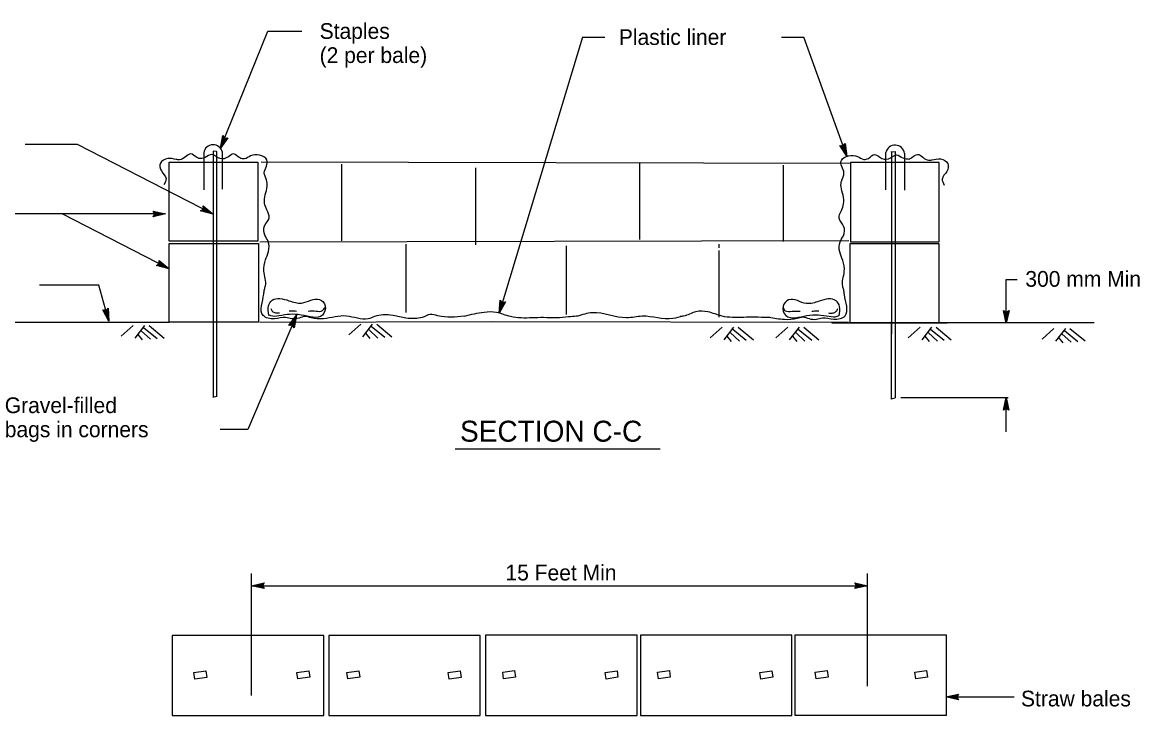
# Model space of a CAD drawing. Extents: x 6707406 to 6714471, y 1868570 to 1872341.
# Drawn here: x 6709428 to 6709939, y 1868969 to 1869287 of the extents above; entities that cross this region are included whole.
import ezdxf

# ---------------------------------------------------------------- set-up
doc = ezdxf.new("R2010")
doc.units = 0
for name, color, linetype in [('1 Control', 7, 'Continuous'), ('56 Stg 3 Anno', 7, 'Continuous'), ('57 Undefined', 7, 'Continuous'), ('59 Soundwall Ann', 7, 'Continuous'), ('60 Nongeo Data', 7, 'Continuous')]:
    doc.layers.add(name, color=color, linetype=linetype)

msp = doc.modelspace()

# ---------------------------------------------------------------- linework, layer by layer
at = {"layer": '1 Control'}
for p, q in [((6709487.66, 1869200.39), (6709487.66, 1869200.39)), ((6709487.66, 1869197.83), (6709487.66, 1869197.83)), ((6709493.42, 1869199.11), (6709493.42, 1869199.11))]:
    msp.add_line(p, q, dxfattribs=at)
msp.add_lwpolyline([(6709487.66, 1869200.39), (6709493.42, 1869199.11), (6709487.66, 1869197.83), (6709487.86, 1869198.17), (6709492.08, 1869199.1), (6709487.86, 1869200.05), (6709488.07, 1869199.71), (6709490.77, 1869199.11), (6709488.07, 1869198.51), (6709488.27, 1869198.85), (6709489.44, 1869199.11), (6709488.27, 1869199.37), (6709488.43, 1869199.11), (6709487.66, 1869197.83), (6709488.43, 1869199.11)], close=True, dxfattribs=at)
at = {"layer": '56 Stg 3 Anno'}
for p, q in [((6709518.59, 1869229.13), (6709540.27, 1869282.85)), ((6709540.27, 1869282.85), (6709555.82, 1869282.85)), ((6709684.34, 1869280.08), (6709646.13, 1869153.7)), ((6709684.34, 1869280.08), (6709694.46, 1869280.08)), ((6709775.45, 1869280.08), (6709785.57, 1869280.08)), ((6709805.29, 1869225.52), (6709785.57, 1869280.08)), ((6709518.59, 1869229.13), (6709519.56, 1869234.95)), ((6709521.94, 1869233.99), (6709518.59, 1869229.13)), ((6709519.08, 1869230.37), (6709519.79, 1869234.61)), ((6709521.54, 1869233.92), (6709519.08, 1869230.36)), ((6709519.56, 1869234.95), (6709519.56, 1869234.95)), ((6709519.56, 1869234.95), (6709520.46, 1869233.76)), ((6709519.58, 1869231.59), (6709520.04, 1869234.33)), ((6709521.14, 1869233.85), (6709519.58, 1869231.59)), ((6709520.08, 1869232.82), (6709520.27, 1869233.99)), ((6709520.77, 1869233.81), (6709520.08, 1869232.82)), ((6709520.46, 1869233.76), (6709521.94, 1869233.99)), ((6709521.94, 1869233.99), (6709521.94, 1869233.99)), ((6709453.01, 1869230.92), (6709429.07, 1869230.92)), ((6709515.11, 1869199.03), (6709453.01, 1869230.92)), ((6709518.59, 1869229.13), (6709518.59, 1869229.13)), ((6709805.29, 1869225.52), (6709802.13, 1869230.5)), ((6709802.13, 1869230.5), (6709802.13, 1869230.5)), ((6709802.13, 1869230.5), (6709803.59, 1869230.21)), ((6709804.83, 1869226.77), (6709802.53, 1869230.41)), ((6709804.39, 1869228.01), (6709802.9, 1869230.36)), ((6709803.94, 1869229.26), (6709803.3, 1869230.27)), ((6709803.59, 1869230.21), (6709804.54, 1869231.37)), ((6709803.79, 1869230.46), (6709803.94, 1869229.26)), ((6709804.04, 1869230.73), (6709804.39, 1869228.01)), ((6709804.29, 1869231.06), (6709804.84, 1869226.77)), ((6709804.54, 1869231.37), (6709804.54, 1869231.37)), ((6709804.54, 1869231.37), (6709805.29, 1869225.52)), ((6709805.29, 1869225.52), (6709805.29, 1869225.52)), ((6709510.67, 1869201.31), (6709510.58, 1869202.8)), ((6709510.58, 1869202.8), (6709510.58, 1869202.8)), ((6709510.58, 1869202.8), (6709515.11, 1869199.03)), ((6709493.42, 1869199.11), (6709417.73, 1869199.11)), ((6709494.96, 1869174), (6709446.06, 1869199.11)), ((6709509.4, 1869200.52), (6709510.67, 1869201.31)), ((6709515.11, 1869199.03), (6709509.4, 1869200.52)), ((6709509.4, 1869200.52), (6709509.4, 1869200.52)), ((6709513.92, 1869199.64), (6709509.76, 1869200.73)), ((6709512.75, 1869200.24), (6709510.07, 1869200.95)), ((6709511.57, 1869200.85), (6709510.42, 1869201.15)), ((6709510.6, 1869202.41), (6709513.93, 1869199.63)), ((6709510.65, 1869202), (6709512.75, 1869200.24)), ((6709510.65, 1869201.62), (6709511.57, 1869200.85)), ((6709515.11, 1869199.03), (6709515.11, 1869199.03)), ((6709490.52, 1869176.28), (6709490.42, 1869177.77)), ((6709490.42, 1869177.77), (6709490.42, 1869177.77)), ((6709490.42, 1869177.77), (6709494.96, 1869174)), ((6709490.45, 1869177.37), (6709493.78, 1869174.6)), ((6709489.25, 1869175.49), (6709490.52, 1869176.28)), ((6709494.96, 1869174), (6709489.25, 1869175.49)), ((6709489.25, 1869175.49), (6709489.25, 1869175.49)), ((6709493.77, 1869174.6), (6709489.61, 1869175.7)), ((6709492.6, 1869175.21), (6709489.91, 1869175.91)), ((6709491.42, 1869175.82), (6709490.27, 1869176.12)), ((6709490.49, 1869176.96), (6709492.6, 1869175.21)), ((6709490.49, 1869176.59), (6709491.42, 1869175.82)), ((6709494.96, 1869174), (6709494.96, 1869174)), ((6709878.28, 1869169.1), (6709883.25, 1869169.1)), ((6709878.28, 1869149.12), (6709878.28, 1869169.1)), ((6709462.84, 1869166.47), (6709435.69, 1869166.47)), ((6709467.42, 1869150.02), (6709462.84, 1869166.47)), ((6709646.13, 1869153.7), (6709646.57, 1869159.58)), ((6709649.03, 1869158.84), (6709646.13, 1869153.7)), ((6709646.51, 1869154.98), (6709646.84, 1869159.27)), ((6709648.64, 1869158.74), (6709646.51, 1869154.97)), ((6709646.57, 1869159.58), (6709646.57, 1869159.58)), ((6709646.57, 1869159.58), (6709647.57, 1869158.48)), ((6709646.9, 1869156.24), (6709647.11, 1869159.01)), ((6709648.24, 1869158.63), (6709646.9, 1869156.24)), ((6709647.28, 1869157.51), (6709647.37, 1869158.69)), ((6709647.88, 1869158.56), (6709647.28, 1869157.51)), ((6709647.57, 1869158.48), (6709649.03, 1869158.84)), ((6709649.03, 1869158.84), (6709649.03, 1869158.84)), ((6709467.42, 1869150.02), (6709464.64, 1869155.23)), ((6709464.64, 1869155.23), (6709464.64, 1869155.23)), ((6709464.64, 1869155.23), (6709466.08, 1869154.83)), ((6709467.06, 1869151.31), (6709465.04, 1869155.11)), ((6709466.71, 1869152.58), (6709465.4, 1869155.03)), ((6709466.35, 1869153.86), (6709465.8, 1869154.91)), ((6709466.08, 1869154.83), (6709467.11, 1869155.92)), ((6709466.29, 1869155.07), (6709466.35, 1869153.86)), ((6709466.57, 1869155.32), (6709466.71, 1869152.58)), ((6709466.84, 1869155.63), (6709467.06, 1869151.3)), ((6709467.11, 1869155.92), (6709467.11, 1869155.92)), ((6709467.11, 1869155.92), (6709467.42, 1869150.02)), ((6709553.27, 1869152.72), (6709531.07, 1869100.43)), ((6709549.84, 1869147.92), (6709553.27, 1869152.72)), ((6709550.23, 1869147.98), (6709552.75, 1869151.5)), ((6709553.27, 1869152.72), (6709552.2, 1869146.92)), ((6709553.27, 1869152.72), (6709553.27, 1869152.72)), ((6709646.13, 1869153.7), (6709646.13, 1869153.7)), ((6709878.28, 1869149.12), (6709877, 1869154.88)), ((6709877, 1869154.88), (6709877, 1869154.88)), ((6709877, 1869154.88), (6709878.28, 1869154.11)), ((6709878.27, 1869150.46), (6709877.34, 1869154.66)), ((6709878.28, 1869151.77), (6709877.68, 1869154.49)), ((6709878.28, 1869153.1), (6709878.02, 1869154.26)), ((6709878.28, 1869154.11), (6709879.56, 1869154.88)), ((6709879.56, 1869154.88), (6709878.28, 1869149.12)), ((6709879.22, 1869154.67), (6709878.28, 1869150.45)), ((6709878.88, 1869154.45), (6709878.28, 1869151.77)), ((6709878.54, 1869154.28), (6709878.28, 1869153.1)), ((6709879.56, 1869154.88), (6709879.56, 1869154.88)), ((6709467.42, 1869150.02), (6709467.42, 1869150.02)), ((6709551.32, 1869148.12), (6709549.84, 1869147.92)), ((6709549.84, 1869147.92), (6709549.84, 1869147.92)), ((6709550.64, 1869148.05), (6709552.23, 1869150.28)), ((6709551.01, 1869148.08), (6709551.71, 1869149.06)), ((6709552.2, 1869146.92), (6709551.32, 1869148.12)), ((6709551.71, 1869149.06), (6709551.5, 1869147.89)), ((6709552.23, 1869150.28), (6709551.73, 1869147.55)), ((6709552.75, 1869151.49), (6709551.97, 1869147.26)), ((6709552.2, 1869146.92), (6709552.2, 1869146.92)), ((6709878.28, 1869149.12), (6709878.28, 1869149.12)), ((6709830.05, 1869114.95), (6709879.14, 1869114.95)), ((6709876.99, 1869109.19), (6709878.28, 1869114.95)), ((6709877.33, 1869109.4), (6709878.27, 1869113.63)), ((6709877.68, 1869109.62), (6709878.27, 1869112.3)), ((6709878.01, 1869109.79), (6709878.27, 1869110.97)), ((6709878.27, 1869112.3), (6709878.87, 1869109.59)), ((6709878.27, 1869110.97), (6709878.53, 1869109.81)), ((6709878.28, 1869114.95), (6709878.28, 1869114.95)), ((6709878.28, 1869114.95), (6709879.55, 1869109.19)), ((6709878.28, 1869099.27), (6709878.28, 1869114.95)), ((6709878.28, 1869113.61), (6709879.21, 1869109.42)), ((6709878.28, 1869109.96), (6709876.99, 1869109.19)), ((6709876.99, 1869109.19), (6709876.99, 1869109.19)), ((6709879.55, 1869109.19), (6709878.28, 1869109.96)), ((6709879.55, 1869109.19), (6709879.55, 1869109.19)), ((6709531.07, 1869100.43), (6709518.32, 1869100.43)), ((6709532.76, 1868978.54), (6709532.76, 1869034.49)), ((6709814.79, 1868982.86), (6709814.79, 1869034.49)), ((6709532.76, 1869028.82), (6709538.52, 1869030.09)), ((6709532.76, 1869028.82), (6709538.52, 1869030.09)), ((6709532.76, 1869028.82), (6709814.79, 1869028.82)), ((6709538.52, 1869027.53), (6709532.76, 1869028.82)), ((6709532.76, 1869028.82), (6709532.76, 1869028.82)), ((6709538.52, 1869027.53), (6709532.76, 1869028.82)), ((6709532.76, 1869028.82), (6709532.76, 1869028.82)), ((6709538.32, 1869027.87), (6709534.09, 1869028.81)), ((6709538.32, 1869027.87), (6709534.09, 1869028.81)), ((6709534.1, 1869028.82), (6709538.3, 1869029.75)), ((6709534.1, 1869028.82), (6709538.3, 1869029.75)), ((6709535.42, 1869028.81), (6709538.13, 1869029.41)), ((6709535.42, 1869028.81), (6709538.13, 1869029.41)), ((6709538.09, 1869028.22), (6709535.42, 1869028.81)), ((6709538.09, 1869028.22), (6709535.42, 1869028.81)), ((6709536.74, 1869028.81), (6709537.9, 1869029.07)), ((6709536.74, 1869028.81), (6709537.9, 1869029.07)), ((6709537.92, 1869028.55), (6709536.74, 1869028.81)), ((6709537.92, 1869028.55), (6709536.74, 1869028.81)), ((6709538.52, 1869030.09), (6709537.76, 1869028.82)), ((6709538.52, 1869030.09), (6709537.76, 1869028.82)), ((6709537.76, 1869028.82), (6709538.52, 1869027.53)), ((6709537.76, 1869028.82), (6709538.52, 1869027.53)), ((6709538.52, 1869030.09), (6709538.52, 1869030.09)), ((6709538.52, 1869030.09), (6709538.52, 1869030.09)), ((6709809.8, 1869028.82), (6709809.03, 1869030.1)), ((6709809.03, 1869030.1), (6709809.03, 1869030.1)), ((6709809.03, 1869030.1), (6709814.79, 1869028.82)), ((6709814.79, 1869028.82), (6709809.03, 1869027.54)), ((6709809.03, 1869027.54), (6709809.8, 1869028.82)), ((6709809.24, 1869029.76), (6709813.47, 1869028.82)), ((6709813.46, 1869028.81), (6709809.26, 1869027.88)), ((6709812.14, 1869028.82), (6709809.43, 1869028.22)), ((6709809.47, 1869029.41), (6709812.14, 1869028.82)), ((6709809.64, 1869029.08), (6709810.82, 1869028.82)), ((6709810.82, 1869028.82), (6709809.66, 1869028.56)), ((6709814.79, 1869028.82), (6709814.79, 1869028.82)), ((6709538.52, 1869027.53), (6709538.52, 1869027.53)), ((6709538.52, 1869027.53), (6709538.52, 1869027.53)), ((6709809.03, 1869027.54), (6709809.03, 1869027.54)), ((6709850.7, 1868977.91), (6709856.46, 1868979.18)), ((6709850.7, 1868977.91), (6709881.9, 1868977.91)), ((6709856.46, 1868976.62), (6709850.7, 1868977.91)), ((6709850.7, 1868977.91), (6709850.7, 1868977.91)), ((6709856.25, 1868976.96), (6709852.03, 1868977.91)), ((6709852.04, 1868977.91), (6709856.24, 1868978.84)), ((6709853.35, 1868977.91), (6709856.07, 1868978.51)), ((6709856.03, 1868977.31), (6709853.35, 1868977.91)), ((6709854.68, 1868977.9), (6709855.84, 1868978.16)), ((6709855.86, 1868977.64), (6709854.68, 1868977.9)), ((6709856.46, 1868979.18), (6709855.69, 1868977.91)), ((6709855.69, 1868977.91), (6709856.46, 1868976.62)), ((6709856.46, 1868979.18), (6709856.46, 1868979.18)), ((6709856.46, 1868976.62), (6709856.46, 1868976.62))]:
    msp.add_line(p, q, dxfattribs=at)
at = {"layer": '57 Undefined'}
msp.add_line((6709625.91, 1869091.56), (6709719.89, 1869091.56), dxfattribs=at)
at = {"layer": '59 Soundwall Ann'}
for p, q in [((6709478.57, 1869148.02), (6709473.1, 1869143.15)), ((6709483.77, 1869147.99), (6709479.25, 1869142.24)), ((6709483.32, 1869147.13), (6709489.51, 1869142.03)), ((6709485.88, 1869147.96), (6709492.8, 1869142.26)), ((6709582.79, 1869148.59), (6709577.31, 1869143.72)), ((6709587.99, 1869148.55), (6709583.47, 1869142.81)), ((6709587.54, 1869147.69), (6709593.73, 1869142.6)), ((6709590.09, 1869148.53), (6709597.02, 1869142.83)), ((6709748.28, 1869147.22), (6709742.8, 1869142.35)), ((6709753.47, 1869147.19), (6709748.95, 1869141.44)), ((6709755.58, 1869147.17), (6709762.5, 1869141.47)), ((6709778.3, 1869147.22), (6709772.82, 1869142.35)), ((6709783.49, 1869147.19), (6709778.97, 1869141.44)), ((6709785.6, 1869147.17), (6709792.52, 1869141.47)), ((6709838.9, 1869147.22), (6709833.42, 1869142.35)), ((6709844.09, 1869147.19), (6709839.58, 1869141.44)), ((6709846.2, 1869147.17), (6709853.13, 1869141.47)), ((6709900.15, 1869146.66), (6709894.68, 1869141.78)), ((6709905.35, 1869146.62), (6709900.83, 1869140.87)), ((6709907.46, 1869146.6), (6709914.38, 1869140.9)), ((6709480.69, 1869143.89), (6709482.67, 1869141.46)), ((6709482.19, 1869145.54), (6709486.42, 1869141.69)), ((6709584.91, 1869144.46), (6709586.89, 1869142.03)), ((6709586.41, 1869146.11), (6709590.64, 1869142.26)), ((6709750.39, 1869143.09), (6709752.37, 1869140.66)), ((6709751.89, 1869144.74), (6709756.12, 1869140.89)), ((6709753.03, 1869146.33), (6709759.22, 1869141.23)), ((6709780.41, 1869143.09), (6709782.39, 1869140.66)), ((6709781.91, 1869144.74), (6709786.14, 1869140.89)), ((6709783.05, 1869146.33), (6709789.23, 1869141.23)), ((6709841.02, 1869143.09), (6709843, 1869140.66)), ((6709842.52, 1869144.74), (6709846.75, 1869140.89)), ((6709843.65, 1869146.33), (6709849.84, 1869141.23)), ((6709902.27, 1869142.52), (6709904.25, 1869140.09)), ((6709903.77, 1869144.17), (6709908, 1869140.32)), ((6709904.9, 1869145.76), (6709911.09, 1869140.66))]:
    msp.add_line(p, q, dxfattribs=at)
at = {"layer": '60 Nongeo Data'}
for p, q in [((6709823.86, 1869229.14), (6709823.86, 1869229.14)), ((6709510.85, 1869227.15), (6709510.85, 1869210.15)), ((6709515.11, 1869227.84), (6709515.11, 1869115.08)), ((6709516.73, 1869227.73), (6709515.11, 1869227.84)), ((6709516.73, 1869227.61), (6709516.73, 1869227.84)), ((6709516.73, 1869227.61), (6709516.73, 1869115.4)), ((6709519.43, 1869210.39), (6709519.43, 1869227.39)), ((6709823.11, 1869210.18), (6709823.11, 1869227.18)), ((6709825.8, 1869227.4), (6709825.8, 1869227.63)), ((6709825.8, 1869227.51), (6709827.42, 1869227.63)), ((6709825.8, 1869227.4), (6709825.8, 1869144.14)), ((6709827.42, 1869227.63), (6709827.42, 1869144.14)), ((6709831.68, 1869226.94), (6709831.68, 1869209.94)), ((6709537.12, 1869222.92), (6709807.06, 1869222.39)), ((6709573.96, 1869221.95), (6709573.96, 1869186.7)), ((6709635.34, 1869220.22), (6709635.34, 1869184.96)), ((6709710.44, 1869222.62), (6709710.44, 1869187.36)), ((6709776.08, 1869221.47), (6709776.08, 1869186.5)), ((6709536.5, 1869186.34), (6709806.17, 1869186.87)), ((6709603.37, 1869185.26), (6709603.37, 1869153.89)), ((6709676.87, 1869184.46), (6709676.87, 1869153.09)), ((6709746.68, 1869185.25), (6709746.68, 1869183.49)), ((6709746.68, 1869182.27), (6709746.68, 1869151.86)), ((6709365.05, 1869149.57), (6709494.96, 1869149.57)), ((6709536.5, 1869149.54), (6709643.26, 1869149.81)), ((6709806.03, 1869149.33), (6709643.26, 1869149.74)), ((6709825.64, 1869149.68), (6709825.64, 1869114.31)), ((6709827.47, 1869149.68), (6709827.47, 1869114.82)), ((6709847.58, 1869149.35), (6709918.59, 1869149.35)), ((6709516.82, 1869115.44), (6709514.99, 1869115.08)), ((6709827.47, 1869114.64), (6709825.64, 1869114.28))]:
    msp.add_line(p, q, dxfattribs=at)
for points in [[(6709494.96, 1869222.81), (6709535.59, 1869222.81), (6709535.59, 1869186.56), (6709494.96, 1869186.56)], [(6709847.58, 1869222.59), (6709806.95, 1869222.59), (6709806.95, 1869186.34), (6709847.58, 1869186.34)], [(6709494.96, 1869185.61), (6709535.89, 1869185.61), (6709535.89, 1869149.57), (6709494.96, 1869149.57)], [(6709847.58, 1869185.4), (6709806.64, 1869185.4), (6709806.64, 1869149.35), (6709847.58, 1869149.35)], [(6709496.47, 1868969.31), (6709565.82, 1868969.31), (6709565.82, 1869006.05), (6709496.47, 1869006.05)], [(6709568.1, 1868969.31), (6709637.45, 1868969.31), (6709637.45, 1869006.05), (6709568.1, 1869006.05)], [(6709639.88, 1868969.38), (6709709.24, 1868969.38), (6709709.24, 1869006.12), (6709639.88, 1869006.12)], [(6709710.76, 1868969.38), (6709780.11, 1868969.38), (6709780.11, 1869006.12), (6709710.76, 1869006.12)], [(6709781.56, 1868969.48), (6709850.91, 1868969.48), (6709850.91, 1869006.23), (6709781.56, 1869006.23)], [(6709506.39, 1868989.01), (6709511.83, 1868989.8), (6709512.26, 1868986.8), (6709506.83, 1868986.01)], [(6709553.5, 1868989.11), (6709558.93, 1868989.9), (6709559.37, 1868986.9), (6709553.94, 1868986.11)], [(6709576.44, 1868989.11), (6709581.87, 1868989.9), (6709582.31, 1868986.9), (6709576.87, 1868986.11)], [(6709622.79, 1868989.01), (6709628.22, 1868989.8), (6709628.66, 1868986.8), (6709623.23, 1868986.01)], [(6709647.74, 1868989.18), (6709653.17, 1868989.97), (6709653.6, 1868986.97), (6709648.17, 1868986.18)], [(6709694.65, 1868989.08), (6709700.08, 1868989.87), (6709700.51, 1868986.87), (6709695.08, 1868986.08)], [(6709718.61, 1868989.18), (6709724.04, 1868989.97), (6709724.48, 1868986.97), (6709719.05, 1868986.18)], [(6709765.52, 1868989.08), (6709770.95, 1868989.87), (6709771.39, 1868986.87), (6709765.95, 1868986.08)], [(6709790.84, 1868989.18), (6709796.27, 1868989.97), (6709796.71, 1868986.97), (6709791.27, 1868986.18)], [(6709836.41, 1868989.18), (6709841.84, 1868989.97), (6709842.27, 1868986.97), (6709836.84, 1868986.18)]]:
    msp.add_lwpolyline(points, close=True, dxfattribs=at)
msp.add_lwpolyline([(6709798.43, 1869149.68), (6709798.43, 1869149.17), (6709851.25, 1869149.17)], dxfattribs=at)
for centre, start, end in [((6709515.15, 1869226.45), 12.0716, 172.0722), ((6709827.39, 1869226.24), 7.9278, 167.9284)]:
    msp.add_arc(centre, 4.36, start, end, dxfattribs=at)
for points in [[(6709508.47, 1869224.6), (6709507.47, 1869225.08), (6709504.91, 1869226.59), (6709502.49, 1869225.23), (6709499.77, 1869223.88), (6709498.26, 1869224.03), (6709494.34, 1869224.48), (6709491.02, 1869222.37), (6709491.47, 1869218.75), (6709493.58, 1869215.28), (6709492.65, 1869212.52)], [(6709630.08, 1869152.2), (6709618.1, 1869152.41), (6709614.47, 1869153.02), (6709610.85, 1869151.66), (6709607.53, 1869151.21), (6709603.45, 1869151.36), (6709597.56, 1869152.57), (6709593.04, 1869152.87), (6709589.11, 1869152.11), (6709586.09, 1869151.06), (6709576.22, 1869152.3), (6709565.71, 1869151.06), (6709559.97, 1869151.51), (6709557.41, 1869152.11), (6709554.53, 1869151.38), (6709551.17, 1869151.07), (6709548.42, 1869151.68), (6709543.22, 1869151.07), (6709538.03, 1869152.6), (6709538.34, 1869162.38), (6709538.64, 1869164.52), (6709539.14, 1869166.13), (6709538.38, 1869172.91), (6709539.14, 1869178.03), (6709540.5, 1869181.95), (6709540.35, 1869186.47), (6709538.84, 1869189.33), (6709538.68, 1869193.7), (6709540.8, 1869197.31), (6709539.74, 1869200.93), (6709538.68, 1869203.94), (6709538.99, 1869207.86), (6709539.89, 1869211.78), (6709539.59, 1869214.64), (6709538.53, 1869217.96), (6709539.59, 1869220.97), (6709539.74, 1869223.83), (6709536.42, 1869225.94), (6709532.34, 1869225.64), (6709529.48, 1869224.29), (6709527.36, 1869224.74), (6709524.49, 1869226.55), (6709522.14, 1869225.24), (6709518.21, 1869224.49), (6709514.44, 1869226.3), (6709511.57, 1869224.94), (6709508.4, 1869224.43)], [(6709769.53, 1869151.74), (6709776.83, 1869150.85), (6709782.56, 1869151.3), (6709785.13, 1869151.9), (6709788.01, 1869151.17), (6709791.37, 1869150.86), (6709794.12, 1869151.47), (6709799.31, 1869150.86), (6709804.51, 1869152.39), (6709804.2, 1869162.17), (6709803.89, 1869164.31), (6709803.4, 1869165.91), (6709804.15, 1869172.69), (6709803.4, 1869177.82), (6709802.04, 1869181.73), (6709802.19, 1869186.25), (6709803.7, 1869189.12), (6709803.85, 1869193.49), (6709801.74, 1869197.1), (6709802.79, 1869200.72), (6709803.85, 1869203.73), (6709803.55, 1869207.65), (6709802.64, 1869211.57), (6709802.94, 1869214.43), (6709804, 1869217.74), (6709802.94, 1869220.76), (6709802.79, 1869223.62), (6709806.12, 1869225.73), (6709810.19, 1869225.43), (6709813.06, 1869224.07), (6709815.17, 1869224.52), (6709818.04, 1869226.33), (6709820.4, 1869225.03), (6709824.32, 1869224.28), (6709828.1, 1869226.09), (6709830.97, 1869224.73), (6709834.14, 1869224.22)], [(6709834.06, 1869224.39), (6709835.06, 1869224.87), (6709837.63, 1869226.38), (6709840.04, 1869225.02), (6709842.76, 1869223.67), (6709844.27, 1869223.82), (6709848.2, 1869224.27), (6709851.52, 1869222.16), (6709851.07, 1869218.54), (6709848.95, 1869215.07), (6709849.88, 1869212.31)], [(6709540.73, 1869152.62), (6709540.54, 1869156.99), (6709542.19, 1869159.54), (6709549.85, 1869159.36), (6709555.69, 1869158.26), (6709563.9, 1869159.9), (6709566.46, 1869156.99), (6709565.18, 1869152.8), (6709555.51, 1869152.8), (6709545.29, 1869152.43), (6709541.64, 1869152.43), (6709540.91, 1869152.8)], [(6709801.81, 1869152.4), (6709801.99, 1869156.78), (6709800.35, 1869159.33), (6709792.68, 1869159.15), (6709786.84, 1869158.05), (6709778.63, 1869159.69), (6709776.08, 1869156.78), (6709777.35, 1869152.59), (6709787.03, 1869152.59), (6709797.25, 1869152.22), (6709800.9, 1869152.22), (6709801.63, 1869152.59)], [(6709541.52, 1869155.82), (6709542.25, 1869154.54), (6709543.71, 1869153.82), (6709545.53, 1869153.82)], [(6709550.03, 1869154.73), (6709552.04, 1869154.73), (6709553.32, 1869154.55)], [(6709558.67, 1869154.61), (6709562.32, 1869154.61), (6709565.24, 1869154.79), (6709566.34, 1869156.43)], [(6709681.79, 1869152.4), (6709681.51, 1869152.34), (6709677.88, 1869151.89), (6709672.45, 1869151.44), (6709666.41, 1869151.59), (6709656.15, 1869151.44), (6709651.32, 1869152.04), (6709644.83, 1869154), (6709639.24, 1869154), (6709630.03, 1869152.19)], [(6709730.16, 1869152.32), (6709725.65, 1869151.13), (6709711.6, 1869152.22), (6709704.48, 1869151.49), (6709688.79, 1869153.86), (6709681.77, 1869152.08)], [(6709770.04, 1869151.7), (6709769.31, 1869151.67), (6709763.27, 1869151.82), (6709753, 1869151.67), (6709748.17, 1869152.28), (6709741.68, 1869154.24), (6709736.1, 1869154.24), (6709730.51, 1869152.28), (6709728.95, 1869152.06)], [(6709783.86, 1869154.4), (6709780.21, 1869154.4), (6709777.29, 1869154.58), (6709776.2, 1869156.22)], [(6709792.5, 1869154.52), (6709790.49, 1869154.52), (6709789.22, 1869154.34)], [(6709801.02, 1869155.61), (6709800.29, 1869154.33), (6709798.83, 1869153.6), (6709797, 1869153.6)]]:
    msp.add_spline(points, degree=3, dxfattribs=at)

# ---------------------------------------------------------------- texts
at = {"layer": '57 Undefined'}
for s, height, p in [('Staples', 7.2, (6709563.92, 1869279.25)), ('Plastic liner', 7.2002, (6709700.91, 1869276.48)), ('(2 per bale)', 7.2002, (6709563.92, 1869268.21)), ('300 mm Min', 7.2, (6709887.03, 1869165.74)), ('Gravel-filled', 7.2002, (6709419.75, 1869107.87)), ('bags in corners', 7.2002, (6709419.75, 1869096.83)), ('SECTION C-C', 9.6002, (6709628.19, 1869094.78)), ('15 Feet Min', 7.2002, (6709649, 1869031.22)), ('Straw bales', 7.2002, (6709885.05, 1868973.54))]:
    msp.add_text(s, height=height, dxfattribs=at).set_placement(p)

doc.saveas('drawing.dxf')
